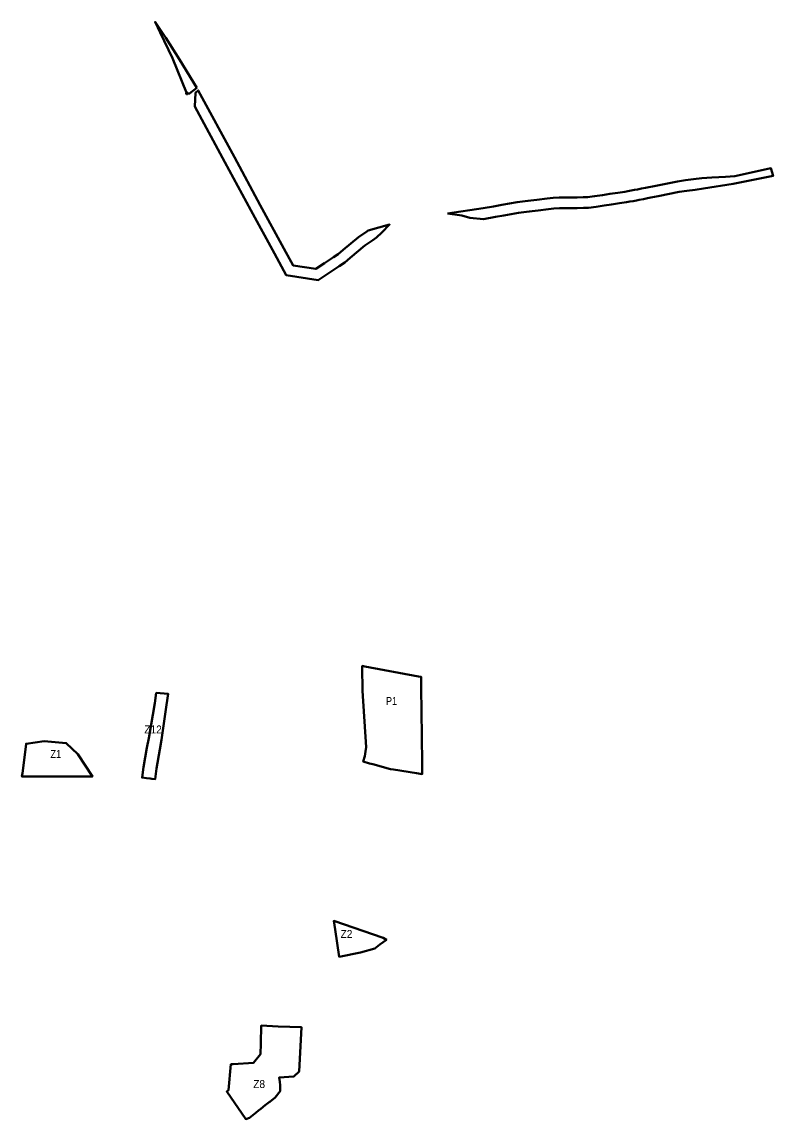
# Model space of a CAD drawing. Extents: x -555426 to -553131, y -1186725 to -1183160.
# Drawn here: x -554609 to -553554, y -1184702 to -1183160 of the extents above; entities that cross this region are included whole.
import ezdxf
from ezdxf.enums import TextEntityAlignment as Align

# ---------------------------------------------------------------- set-up
doc = ezdxf.new("R2010")
doc.units = 0
doc.header["$LTSCALE"] = 4.5
doc.header["$PDMODE"] = 32
doc.header["$PDSIZE"] = 2.25
for name, color, linetype, lineweight in [('12', 7, 'Continuous', 40), ('2', 7, 'Continuous', 40), ('4', 7, 'Continuous', 40), ('48', 7, 'Continuous', 40), ('62', 7, 'Continuous', 25), ('8', 7, 'Continuous', 40)]:
    doc.layers.add(name, color=color, linetype=linetype, lineweight=lineweight)
doc.layers.add('60', color=7, linetype='Continuous')
doc.layers.add('61', color=7, linetype='Continuous')

msp = doc.modelspace()

# ---------------------------------------------------------------- linework, layer by layer
at = {"layer": '12'}
msp.add_lwpolyline([(-554216.082, -1184572.657), (-554219.51, -1184635.3), (-554226.98, -1184642.35), (-554247.47, -1184643.35), (-554246.78, -1184649.63), (-554246.31, -1184654.17), (-554245.93, -1184662.76), (-554253.15, -1184671.5), (-554260.66, -1184677.77), (-554261.49, -1184678.42), (-554267.01, -1184682.66), (-554273.25, -1184687.46), (-554276.41, -1184689.96), (-554280.002, -1184692.844), (-554289.4, -1184700.39), (-554294.55, -1184701.98), (-554321.096, -1184663.282), (-554318.775, -1184661.419), (-554315.201, -1184624.889), (-554312.325, -1184624.733), (-554283.78, -1184623.18), (-554273.897, -1184610.896), (-554273.46, -1184595.6), (-554272.744, -1184570.534), (-554248.927, -1184572.119)], close=True, dxfattribs=at)
at = {"layer": '2'}
for points in [[(-554535.41, -1184220.79), (-554526.4, -1184220.82), (-554519.59, -1184220.81), (-554509.93, -1184220.84), (-554530.2, -1184189.32), (-554546.63, -1184173.61), (-554577.52, -1184171.17), (-554602.96, -1184174.54), (-554607.39, -1184209.02), (-554608.27, -1184215.84), (-554608.89, -1184220.71), (-554597.59, -1184220.73), (-554570.19, -1184220.76)], [(-554570.19, -1184220.76), (-554559.89, -1184220.77), (-554535.41, -1184220.79)]]:
    msp.add_lwpolyline(points, dxfattribs=at)
msp.add_lwpolyline([(-554163.2, -1184474.11), (-554169.02, -1184435.57), (-554170.7, -1184423.54), (-554101.44, -1184447.55), (-554096.79, -1184449.95), (-554106.24, -1184456.86), (-554113.17, -1184462.37), (-554133.03, -1184467.75)], close=True, dxfattribs=at)
at = {"layer": '4'}
msp.add_lwpolyline([(-554054.44, -1184215.95), (-554046.46, -1184217.21), (-554046.49, -1184214.37), (-554047.25, -1184151.79), (-554047.37, -1184141.38), (-554048.13, -1184084.31), (-554048.18, -1184080.56), (-554051.69, -1184079.91), (-554127.06, -1184066.03), (-554130.79, -1184065.34), (-554130.94, -1184066.61), (-554130.56, -1184100.41), (-554125.32, -1184179.55), (-554126.18, -1184185.43), (-554127.18, -1184192.25), (-554129.31, -1184199.7), (-554120.6, -1184202.17), (-554115.94, -1184203.49), (-554091.23, -1184210.19), (-554086.75, -1184210.89)], close=True, dxfattribs=at)
at = {"layer": '48'}
msp.add_line((-553665.24, -1183381.36), (-553676.67, -1183382.9), dxfattribs=at)
for points in [[(-554363.18, -1183253.13), (-554387.431, -1183213.215), (-554406.75, -1183182.832), (-554421.72, -1183160.34), (-554414.65, -1183175.07), (-554397.33, -1183211.12), (-554377.12, -1183260.83)], [(-554377.12, -1183260.83), (-554373.37, -1183261.05), (-554363.18, -1183253.13)], [(-554110.58, -1183463.31), (-554103.48, -1183456.27), (-554092.27, -1183445.06), (-554122.231, -1183453.201), (-554124.207, -1183454.614), (-554136.184, -1183462.634), (-554157.583, -1183480.555), (-554164.408, -1183486.48), (-554171.218, -1183490.925), (-554184.025, -1183499.312), (-554196.042, -1183507.394), (-554228.053, -1183502.414), (-554240.95, -1183478.721), (-554274.264, -1183417.699), (-554310.485, -1183350.454), (-554361.077, -1183256.605), (-554365.04, -1183259.86), (-554366.04, -1183279.01), (-554323.69, -1183357.57), (-554287.45, -1183424.85), (-554254.12, -1183485.9)], [(-553943.503, -1183434.312), (-553932.051, -1183432.172), (-553911.142, -1183428.372), (-553896.168, -1183426.715), (-553883.573, -1183425.111), (-553869.084, -1183423.282), (-553861.405, -1183422.316), (-553853.741, -1183422.198), (-553845.312, -1183422.059), (-553837.037, -1183421.999), (-553828.747, -1183421.868), (-553820.02, -1183421.688), (-553813.001, -1183421.608), (-553802.104, -1183420.04), (-553791.062, -1183418.375), (-553780.765, -1183416.848), (-553769.471, -1183415.181), (-553759.583, -1183413.737), (-553754.87, -1183412.847), (-553750.223, -1183412.031), (-553745.572, -1183411.128), (-553741.554, -1183410.472), (-553735.462, -1183409.258), (-553729.823, -1183408.041), (-553725.417, -1183407.201), (-553720.004, -1183406.234), (-553715.047, -1183405.105), (-553685.3, -1183399.258), (-553674.627, -1183397.76), (-553663.208, -1183396.222), (-553651.335, -1183394.575), (-553609.73, -1183387.865), (-553553.598, -1183376.687), (-553556.6, -1183365.96), (-553607.36, -1183376.83), (-553620.62, -1183377.81), (-553629.85, -1183378.3), (-553639.56, -1183378.81), (-553653.56, -1183379.74), (-553665.24, -1183381.36)], [(-553676.67, -1183382.9), (-553687.79, -1183384.46), (-553718.16, -1183390.43), (-553722.99, -1183391.53), (-553728.14, -1183392.45), (-553732.81, -1183393.34), (-553738.51, -1183394.57), (-553744.23, -1183395.71), (-553748.21, -1183396.36), (-553752.95, -1183397.28), (-553757.56, -1183398.09), (-553762.06, -1183398.94), (-553771.65, -1183400.34), (-553782.96, -1183402.01), (-553793.28, -1183403.54), (-553804.29, -1183405.2), (-553814.16, -1183406.62), (-553820.26, -1183406.69)], [(-553820.26, -1183406.69), (-553829.02, -1183406.87), (-553837.21, -1183407), (-553845.49, -1183407.06), (-553853.98, -1183407.2), (-553862.46, -1183407.33), (-553870.96, -1183408.4), (-553885.46, -1183410.23), (-553897.94, -1183411.82), (-553913.31, -1183413.52)], [(-553913.31, -1183413.52), (-553934.77, -1183417.42), (-553946.22, -1183419.56), (-553961.04, -1183422.25), (-554011.181, -1183429.704)], [(-554011.181, -1183429.704), (-553990.975, -1183432.278), (-553979.461, -1183435.498), (-553960.428, -1183437.384), (-553943.503, -1183434.312)], [(-554254.12, -1183485.9), (-554254.12, -1183485.9), (-554237.684, -1183516.096), (-554192.544, -1183523.119), (-554175.73, -1183511.81), (-554163.01, -1183503.48), (-554155.35, -1183498.48), (-554147.85, -1183491.97), (-554127.17, -1183474.65), (-554115.67, -1183466.95), (-554110.58, -1183463.31)]]:
    msp.add_lwpolyline(points, dxfattribs=at)
msp.add_point((-554377.12, -1183260.83), dxfattribs=at)
at = {"layer": '62'}
for points in [[(-554054.44, -1184215.95), (-554046.46, -1184217.21), (-554046.49, -1184214.37), (-554047.25, -1184151.79), (-554047.37, -1184141.38), (-554048.18, -1184080.56), (-554051.69, -1184079.91), (-554127.06, -1184066.03), (-554130.79, -1184065.34), (-554130.94, -1184066.61), (-554130.56, -1184100.41), (-554125.32, -1184179.55), (-554126.18, -1184185.43), (-554127.18, -1184192.25), (-554129.31, -1184199.7), (-554115.94, -1184203.49), (-554091.23, -1184210.19), (-554086.75, -1184210.89), (-554052.356, -1184216.276)], [(-554415.38, -1184182.72), (-554413.02, -1184168.92), (-554405.62, -1184120.08), (-554403.37, -1184104.58), (-554420.12, -1184103.06), (-554422.41, -1184117.71), (-554430.77, -1184166.73), (-554433.24, -1184180.51), (-554438.09, -1184207.49), (-554440.16, -1184222.12), (-554434.03, -1184222.84), (-554428.6, -1184223.48), (-554426.63, -1184223.71), (-554421.69, -1184224.28), (-554419.97, -1184209.57), (-554414.982, -1184180.391)], [(-554163.2, -1184474.11), (-554169.02, -1184435.57), (-554170.7, -1184423.54), (-554101.44, -1184447.55), (-554096.79, -1184449.95), (-554106.24, -1184456.86), (-554113.17, -1184462.37), (-554133.03, -1184467.75), (-554164.103, -1184474.3)], [(-554216.082, -1184572.657), (-554219.51, -1184635.3), (-554226.98, -1184642.35), (-554247.47, -1184643.35), (-554246.78, -1184649.63), (-554246.31, -1184654.17), (-554245.93, -1184662.76), (-554253.15, -1184671.5), (-554260.66, -1184677.77), (-554261.49, -1184678.42), (-554267.01, -1184682.66), (-554273.25, -1184687.46), (-554276.41, -1184689.96), (-554280.002, -1184692.844), (-554289.4, -1184700.39), (-554294.55, -1184701.98), (-554321.096, -1184663.282), (-554318.775, -1184661.419), (-554315.201, -1184624.889), (-554312.325, -1184624.733), (-554283.78, -1184623.18), (-554273.897, -1184610.896), (-554273.46, -1184595.6), (-554272.744, -1184570.534), (-554248.927, -1184572.119), (-554215.254, -1184572.671)]]:
    msp.add_lwpolyline(points, dxfattribs=at)
msp.add_lwpolyline([(-554535.41, -1184220.79), (-554559.89, -1184220.77), (-554570.19, -1184220.76), (-554597.59, -1184220.73), (-554608.89, -1184220.71), (-554608.27, -1184215.84), (-554607.39, -1184209.02), (-554602.96, -1184174.54), (-554577.52, -1184171.17), (-554546.63, -1184173.61), (-554530.2, -1184189.32), (-554509.93, -1184220.84), (-554519.59, -1184220.81), (-554526.4, -1184220.82)], close=True, dxfattribs=at)
at = {"layer": '8'}
msp.add_lwpolyline([(-554415.38, -1184182.72), (-554413.02, -1184168.92), (-554405.62, -1184120.08), (-554403.37, -1184104.58), (-554420.12, -1184103.06), (-554422.41, -1184117.71), (-554430.77, -1184166.73), (-554433.24, -1184180.51), (-554438.09, -1184207.49), (-554440.16, -1184222.12), (-554434.03, -1184222.84), (-554428.6, -1184223.48), (-554426.63, -1184223.71), (-554421.69, -1184224.28), (-554419.97, -1184209.57)], close=True, dxfattribs=at)

# ---------------------------------------------------------------- texts
at = {"layer": '60'}
for s, width, p in [('Z12', 0.95, (-554424.722, -1184160.184)), ('Z1', 0.85, (-554561.25, -1184194.588)), ('Z2', 0.95, (-554152.946, -1184447.571)), ('Z8', 0.95, (-554275.63, -1184658.428))]:
    msp.add_text(s, height=11.25, dxfattribs=dict(at, width=width)).set_placement(p, align=Align.CENTER)
at = {"layer": '61', "width": 0.85}
msp.add_text('P1', height=11.25, dxfattribs=at).set_placement((-554089.635, -1184120.154), align=Align.CENTER)

doc.saveas('drawing.dxf')
